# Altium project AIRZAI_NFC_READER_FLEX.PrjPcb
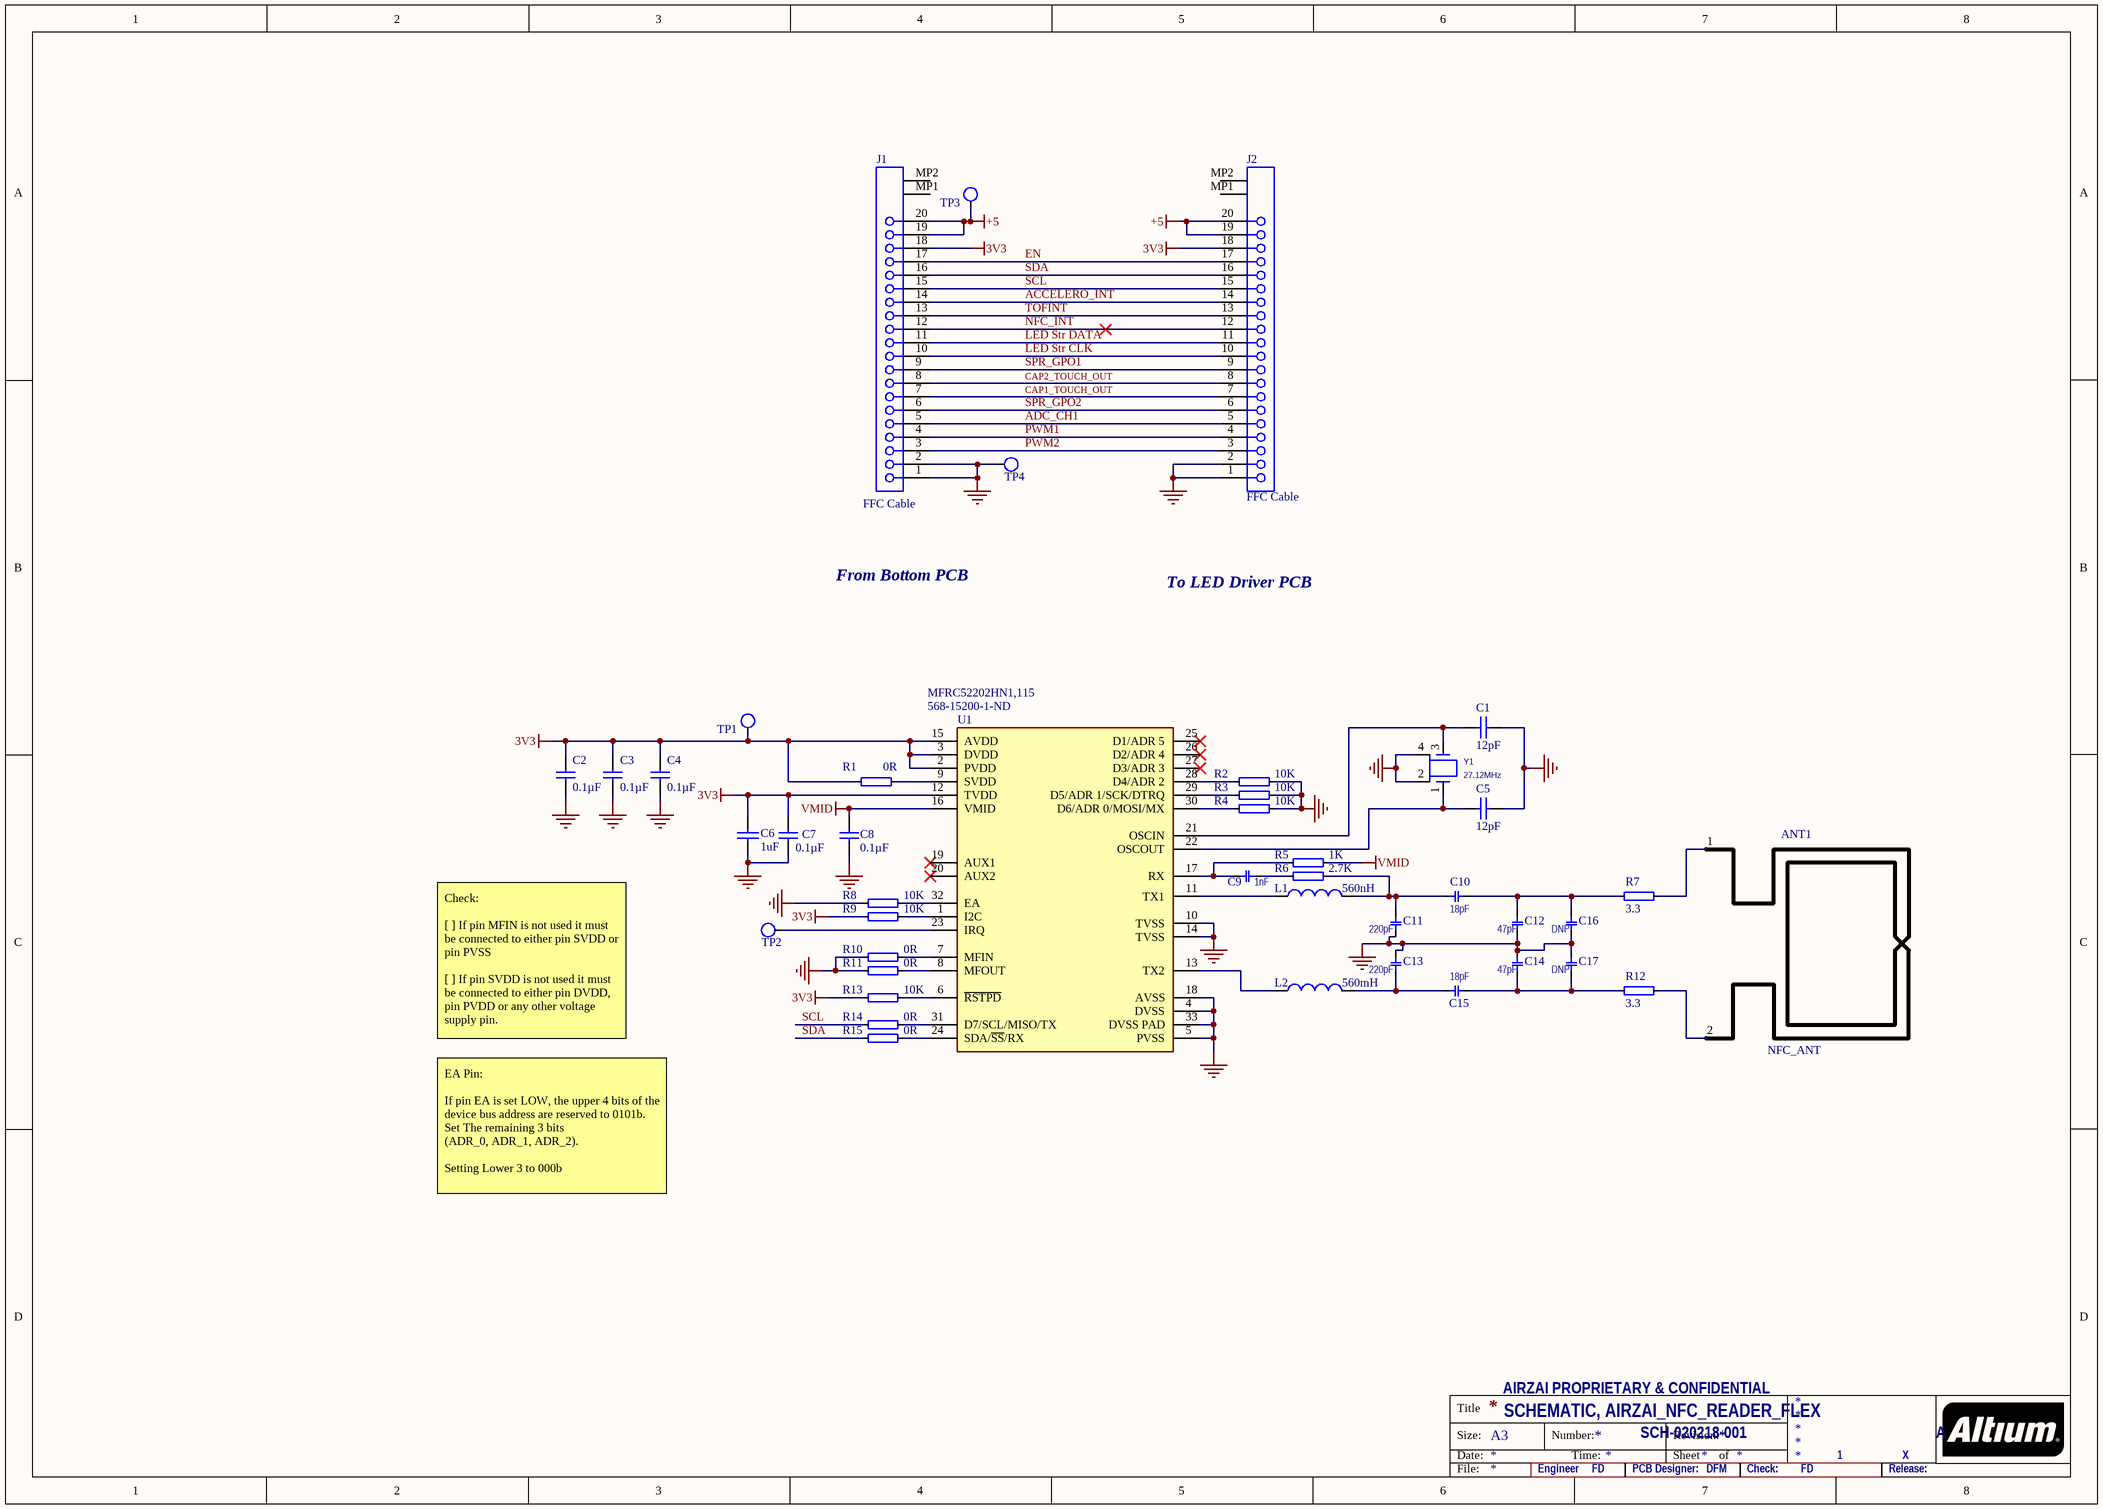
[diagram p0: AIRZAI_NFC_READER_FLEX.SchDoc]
1 sheet, 43 parts. Net scope: global (net labels, ports and power ports of the same name join across sheets).
Board file: AIRZAI_NFC_READER_FLEX.PcbDoc

## Sheet AIRZAI_NFC_READER_FLEX.SchDoc
size A3

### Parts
ANT1  NFC_ANT  [ANTENNA-NFC-60MMX30MM]
C1  12pF  [0402CAP]
C2  0.1µF  [0402CAP]
C3  0.1µF  [0402CAP]
C4  0.1µF  [0402CAP]
C5  12pF  [0402CAP]
C6  1uF  [CAPC0402(1005)60_M]
C7  0.1µF  [0402CAP]
C8  0.1µF  [0402CAP]
C9  1nF  [0402CAP]
C10  18pF  [0402CAP]
C11  220pF  [0402CAP]
C12  47pF  [0402CAP]
C13  220pF  [0402CAP]
C14  47pF  [0402CAP]
C15  18pF  [0402CAP]
C16  DNP  [0402CAP]
C17  DNP  [0402CAP]
J1  FFC Cable  [FFC_Pads_MBD]
J2  FFC Cable  [FFC_Pads_LID]
L1  560nH  [0603CAP]
L2  560mH  [0603CAP]
R1  0R  [0402]
R2  10K  [0402]
R3  10K  [0402]
R4  10K  [0402]
R5  1K  [0402]
R6  2.7K  [0402]
R7  3.3  [0603]
R8  10K  [0402]
R9  10K  [0402]
R10  0R  [0402]
R11  0R  [0402]
R12  3.3  [0603]
R13  10K  [0402]
R14  0R  [0402]
R15  0R  [0402]
TP1  WIREPT  [TP_0.9MM]  (value not drawn)
TP2  WIREPT  [TP_0.9MM]  (value not drawn)
TP3  WIREPT  [TP_0.9MM]  (value not drawn)
TP4  WIREPT  [TP_0.9MM]  (value not drawn)
U1  Supplier Part Number 1: 568-15200-1-ND  [VFQFN-32-MFRC52202HN1,157]  (hidden comment: MFRC52202HN1,115)
Y1  27.12MHz  [XTAL_2016]

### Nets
3V3: C2.1 C3.1 C4.1 C6.2 C7.1 J1.18 J2.18 R1.2 R9.2 R13.2 TP1.1 U1.2(PVDD) U1.3(DVDD) U1.12(TVDD) U1.15(AVDD)
+5: J1.19 J1.20 J2.19 J2.20 TP3.1
GND: C1.1 C2.2 C3.2 C4.2 C5.1 C6.1 C7.2 C8.2 C11.1 C12.1 C13.2 C14.2 C16.1 C17.2 J1.1 J1.2 J2.1 J2.2 R2.1 R3.1 R4.1 R8.2 R10.2 R11.2 TP4.1 U1.4(DVSS) U1.5(PVSS) U1.10(TVSS) U1.14(TVSS) U1.18(AVSS) U1.33(DVSS_PAD) Y1.2 Y1.4
VMID: C8.1 R5.1 U1.16(VMID)
ACCELERO_INT: J1.14 J2.14
ADC_CH1: J1.5 J2.5
CAP1_TOUCH_OUT: J1.7 J2.7
CAP2_TOUCH_OUT: J1.8 J2.8
EN: J1.17 J2.17
LED Str CLK: J1.10 J2.10
LED Str DATA: J1.11 J2.11
NFC_INT: J1.12 J2.12
PWM1: J1.4 J2.4
PWM2: J1.3 J2.3
SCL: J1.15 J2.15 R14.2
SDA: J1.16 J2.16 R15.2
SPR_GPO1: J1.9 J2.9
SPR_GPO2: J1.6 J2.6
TOFINT: J1.13 J2.13
NetANT1_1: ANT1.1 R7.1
NetANT1_2: ANT1.2 R12.1
NetC1_2: C1.2 U1.21(OSCIN) Y1.3
NetC5_2: C5.2 U1.22(OSCOUT) Y1.1
NetC9_1: C9.1 R6.2
NetC9_2: C9.2 R5.2 U1.17(RX)
NetC10_1: C10.1 C12.2 C16.2 R7.2
NetC10_2: C10.2 C11.2 L1.2 R6.1
NetC13_1: C13.1 C15.2 L2.2
NetC14_1: C14.1 C15.1 C17.1 R12.2
NetL1_1: L1.1 U1.11(TX1)
NetL2_1: L2.1 U1.13(TX2)
NetR1_1: R1.1 U1.9(SVDD)
NetR2_2: R2.2 U1.28(D4/ADR_2)
NetR3_2: R3.2 U1.29(D5/ADR_1/SCK/DTRQ)
NetR4_2: R4.2 U1.30(D6/ADR_0/MOSI/MX)
NetR8_1: R8.1 U1.32(EA)
NetR9_1: R9.1 U1.1(I2C)
NetR10_1: R10.1 U1.7(MFIN)
NetR11_1: R11.1 U1.8(MFOUT)
NetR13_1: R13.1 U1.6(~{RSTPD})
NetR14_1: R14.1 U1.31(D7/SCL/MISO/TX)
NetR15_1: R15.1 U1.24(SDA/~{SS}/RX)
NetTP2_1: TP2.1 U1.23(IRQ)

Not connected (* = marked no-connect by the designer): J1 MP1 MP2; J2 MP1 MP2; U1 19(AUX1)* 20(AUX2)* 25(D1/ADR_5)* 26(D2/ADR_4)* 27(D3/ADR_3)*

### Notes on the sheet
- From Bottom PCB
- To LED Driver PCB
- Check:
  [ ] If pin MFIN is not used it must be connected to either pin SVDD or pin PVSS
  [ ] If pin SVDD is not used it must be connected to either pin DVDD, pin PVDD or any other voltage supply pin.
- EA Pin:
  If pin EA is set LOW, the upper 4 bits of the device bus address are reserved to 0101b. Set The remaining 3 bits
  (ADR_0, ADR_1, ADR_2).
  Setting Lower 3 to 000b
- AIRZAI PROPRIETARY & CONFIDENTIAL
- SCHEMATIC, AIRZAI_NFC_READER_FLEX
- SCH-020218-001
- 1
- X
- A
- Engineer
- FD
- PCB Designer:
- DFM
- Check:
- Release:

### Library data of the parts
C1 C5 = CAP: CAP CER 12PF 50V C0G/NP0 0402; Manufacturer: KEMET; Manufacturer Part Number: C0402C120J5GACTU; Dielectric Material: Ceramic; Tolerance: 5%; Dielectric: C0G; Temperature Coefficient: 30ppm/°C
C2-C4 C7 C8 = C0402-100n: Capacitor, X7R, ±10%; Manufacturer: TDK; Manufacturer Part Number: C1005X7R1C104K; Note: 16V ±10% X7R; Case-EIA: 0402; Case-Metric: 1005; Rated Voltage: 16 V; Tolerance: Â±20%
C6 = CAP: CAP 1uF 16V ±10% 0402 (1005 Metric) Thickness 0.6mm SMD; Manufacturer: Taiyo Yuden; Manufacturer Part Number: EMK105BJ105KV-F; Dielectric: X5R
C9 = 56p: CAP CER 1000PF 50V C0G/NP0 0402; Manufacturer: Murata; Manufacturer Part Number: GRM1555C1H102FA01D; Material: Ceramic; Tolerance: 1%; Dielectric: C0G
C10 C15 = 56p: CAP CER 18PF 50V NP0 0402; Manufacturer: Kyocera AVX; Manufacturer Part Number: 04025U180FAT2A; Tolerance: 1%; Dielectric: C0G
C11 C13 = 56p: CAP CER 220PF 50V NPO 0402; Manufacturer: Yageo; Manufacturer Part Number: CC0402FRNPO9BN221; Tolerance: 1%; Dielectric: C0G
C12 C14 = 56p: CAP CER 47PF 50V C0G/NP0 0402; Manufacturer: Murata; Manufacturer Part Number: GJM1555C1H470FB01D; Tolerance: 1%; Dielectric: C0G
C16 C17 = 56p
J1 J2 = XF2M-2015-1A-R100: Cable
L1 L2 = Inductor: FIXED IND 560NH 100MA 1.05 OHM; Manufacturer: TDK; Manufacturer Part Number: MLF1608DR56JTD25; Core Material: Ferrite; Tolerance: 5%; DC Resistance (DCR): 1.05R; Shielding: Shielded; Self Resonant Frequency: 170MHz; Test Frequency: 25MHz; Max DC Current: 30mA; Q Factor: 35
R1 R10 R11 R14 R15 = R0402-12k: Resistor, ±1%, 0.063W; Manufacturer: Panasonic; Manufacturer Part Number: ERJ-2GE0R00X; Note: 0.1W JUMPER; Case-Metric: 1005; Tolerance: ±5%
R2-R4 R8 R9 R13 = R0402-12k: Resistor 10K, ±1%, 0.063W; Manufacturer: Vishay Dale; Manufacturer Part Number: CRCW040210K0JNED; Resistance: 10kR; Power Rating: 63mW; Tolerance: 5%; Voltage Rating: 50V; Temperature Coefficient: 200ppm/°C
R5 = R0402-12k: RES SMD 1K OHM 1% 1/16W 0402; Manufacturer: Yageo; Manufacturer Part Number: RC0402FR-071KL; Resistance: 1kR; Temperature Coefficient: 100ppm/°C; Power Rating: 62.5mW; Voltage Rating (DC): 50V
R6 = R0402-12k: RES SMD 2.7K OHM 1% 1/16W 0402; Manufacturer: Yageo Phycomp; Manufacturer Part Number: RC0402FR-072K7L; Power Rating: 63mW; Temperature Coefficient: 100ppm/°C; Resistance: 2.7kR; Voltage Rating (DC): 50V
R7 R12 = R0402-12k: RES SMD 3.3 OHM 1% 1/10W 0603; Manufacturer: Yageo; Manufacturer Part Number: AC0603FR-073R3L; Resistance: 3.3R; Max Power Dissipation: 100mW; Temperature Coefficient: 200ppm/°C
U1 = MFRC52201HN1,157: IC RFID READER 13.56MHZ 32HVQFN; Manufacturer: NXP Semiconductors
Y1 = ZTB_2: CRYSTAL 27.12MHZ 10PF SMD; Manufacturer: ECS International; Manufacturer Part Number: ECS-271.2-10-37-CKM-TR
